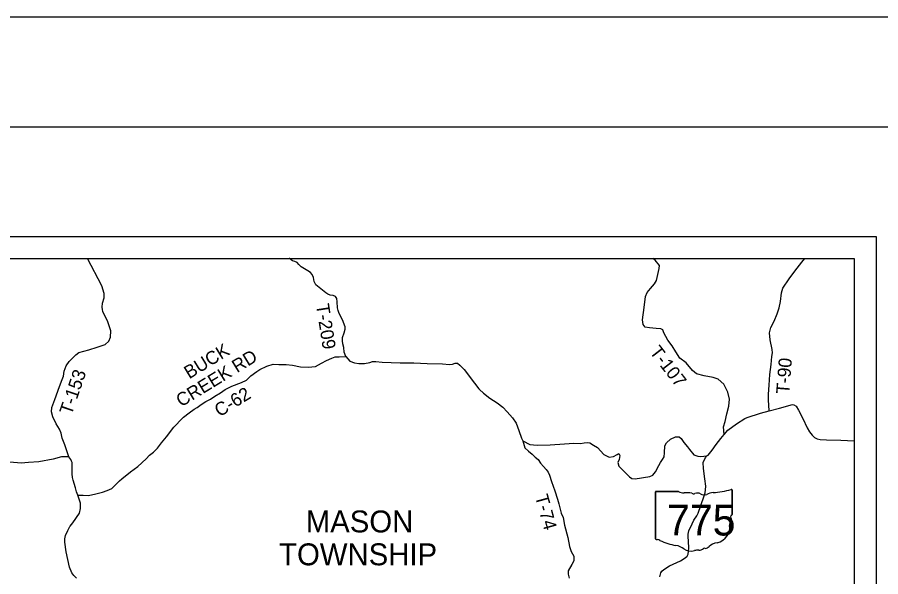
# Model space of a CAD drawing. Extents: x -6.4 to 34, y -1.2 to 22.
# Drawn here: x 5.084 to 9.021, y 19.448 to 22 of the extents above; entities that cross this region are included whole.
import ezdxf

# ---------------------------------------------------------------- set-up
doc = ezdxf.new("R2010")
doc.units = 0
for name, color, linetype in [('GM_X_County', 7, 'Continuous'), ('GM_X_County_ROW', 7, 'Continuous'), ('GM_X_Minor_Lake', 7, 'Continuous'), ('GM_X_Minor_River', 7, 'Continuous'), ('GM_X_Minor_River_Text', 7, 'Continuous'), ('GM_X_Section', 7, 'Continuous'), ('GM_X_Township', 7, 'Continuous'), ('GM_X_Township_Road', 7, 'Continuous'), ('GM_X_Township_Subdivision', 7, 'Continuous'), ('GM_X_Township_Subdivision_Text', 7, 'Continuous'), ('GM_X_Township_Text', 7, 'Continuous')]:
    doc.layers.add(name, color=color, linetype=linetype)

msp = doc.modelspace()

# ---------------------------------------------------------------- linework, layer by layer
at = {"layer": 'GM_X_County'}
msp.add_lwpolyline([(1.5, 21.5), (33.5, 21.5), (33.5, 0.5), (1.5, 0.5)], close=True, dxfattribs=at)
at = {"layer": 'GM_X_County_ROW'}
for p, q in [((7.9936, 19.8336), (7.9936, 19.621)), ((8.0996, 19.8372), (7.9971, 19.8372)), ((8.3437, 19.7313), (8.3437, 19.8425)), ((8.3437, 19.7313), (8.3437, 19.7313))]:
    msp.add_line(p, q, dxfattribs=at)
for centre, major_axis, start_param, end_param in [((8.219, 20.1271), (0.3713, 0), 4.814394, 5.042369), ((8.3398, 19.843), (0.0039, 0), 6.141152, 7.989035), ((7.9976, 19.834), (0.00406, 0), 1.712693, 3.28349), ((8.124, 19.8619), (0.0393, 0), 4.042523, 4.731795), ((8.1371, 19.7179), (0.1412, 0), 1.404758, 1.657858), ((8.1691, 19.8351), (0.0113, 0), 3.836095, 5.185415), ((8.1858, 19.8106), (0.0236, 0), 0.950623, 2.079405), ((8.2162, 19.8443), (0.0284, 0), 4.081561, 5.145723), ((8.2664, 19.7723), (0.0747, 0), 1.699011, 2.107814), ((8.3396, 19.7309), (0.00417, 0), 5.05454, 6.418171), ((8.3577, 19.6848), (0.0263, 0), 2.387724, 3.262537), ((8.3428, 19.7232), (0.00603, 0), 1.883978, 3.671073), ((8.3045, 19.7091), (0.0362, 0), 5.934695, 6.695948), ((8.2398, 19.6706), (0.0929, 0), 5.101752, 6.440018), ((7.9977, 19.6206), (0.00409, 0), 3.00124, 4.508301), ((7.9983, 19.6423), (0.0312, 0), 4.665946, 4.897461), ((8.0047, 19.6088), (0.0113, 0), 0.519207, 1.627899), ((8.1468, 19.7997), (0.2681, 0), 4.195997, 4.488961), ((8.0669, 19.5255), (0.0839, 0), 0.823519, 1.323587), ((8.1576, 19.6077), (0.0532, 0), 4.026481, 4.996735), ((8.1923, 19.5918), (0.0284, 0), 4.691044, 5.507374), ((8.2179, 19.5712), (0.00798, 0), 1.147584, 2.315152), ((8.2145, 19.6004), (0.03, 0), 4.937069, 5.64225), ((8.279, 19.5613), (0.0509, 0), 1.647645, 2.488434), ((8.1884, 19.5342), (0.0437, 0), 1.495662, 1.94098)]:
    msp.add_ellipse(centre, major_axis=major_axis, ratio=0.8, start_param=start_param, end_param=end_param, dxfattribs=at)
at = {"layer": 'GM_X_Minor_Lake'}
for points in [[(8.014, 19.4471), (8.0188, 19.4653), (8.0231, 19.4728), (8.0331, 19.481), (8.0579, 19.4977), (8.1083, 19.5209), (8.1301, 19.5342), (8.139, 19.5417), (8.1433, 19.5515), (8.1459, 19.5777), (8.1445, 19.6107), (8.1433, 19.6293), (8.1434, 19.6415), (8.1471, 19.6566), (8.1616, 19.6891), (8.169, 19.706), (8.1822, 19.7252), (8.1892, 19.738), (8.2146, 19.8124), (8.2205, 19.8309), (8.2226, 19.8438), (8.2232, 19.8609), (8.2199, 19.8947), (8.213, 19.9423), (8.2115, 19.9696), (8.2229, 19.9915), (8.2291, 19.9998), (8.234, 20.0031), (8.2529, 20.0259), (8.2703, 20.0504), (8.2927, 20.0785), (8.307, 20.097), (8.3236, 20.1168), (8.3638, 20.1447), (8.4025, 20.1703), (8.4124, 20.1747), (8.4737, 20.1943), (8.5133, 20.2051), (8.5594, 20.2169), (8.5974, 20.2278), (8.6127, 20.2317), (8.6195, 20.2328), (8.6259, 20.2319), (8.6353, 20.2253), (8.6468, 20.2073), (8.6663, 20.1694), (8.6866, 20.127), (8.6962, 20.1086), (8.7085, 20.0929), (8.7201, 20.0832), (8.7313, 20.077), (8.7449, 20.0737), (8.7737, 20.0725), (8.8401, 20.0712), (8.9, 20.067)], [(5.3515, 19.8467), (5.3499, 19.8532), (5.3386, 19.8876), (5.3354, 19.9002), (5.3341, 19.9165), (5.3336, 19.9605), (5.3334, 19.9685), (5.3316, 19.9746), (5.3283, 19.9823), (5.3193, 19.9942), (5.3148, 19.9946), (5.2985, 19.9952), (5.2852, 19.9947), (5.2468, 19.9842), (5.1822, 19.9715), (5.1351, 19.9688), (5.101, 19.9666), (5.0495, 19.9712)], [(5.3241, 19.6767), (5.325, 19.6782), (5.3377, 19.6932), (5.3672, 19.7372), (5.372, 19.7591), (5.3724, 19.7827), (5.3598, 19.8192), (5.3545, 19.8346), (5.3515, 19.8467)], [(5.3537, 19.4409), (5.3414, 19.4536), (5.3329, 19.4663), (5.3223, 19.4922), (5.3066, 19.5608), (5.3008, 19.6057), (5.301, 19.6201), (5.3039, 19.6356), (5.3145, 19.659), (5.3195, 19.6682), (5.3241, 19.6767)]]:
    msp.add_lwpolyline(points, dxfattribs=at)
at = {"layer": 'GM_X_Minor_River'}
for points in [[(6.176, 20.3834), (6.1761, 20.3834), (6.1906, 20.3938), (6.2224, 20.4087), (6.2511, 20.4172), (6.2769, 20.4166), (6.3102, 20.4164), (6.3383, 20.4123), (6.3747, 20.406), (6.4107, 20.4039), (6.4433, 20.4075), (6.4716, 20.4217), (6.4943, 20.434), (6.5181, 20.4451), (6.5329, 20.4509), (6.5522, 20.4506), (6.5825, 20.4519), (6.6008, 20.4311), (6.6213, 20.4232), (6.6418, 20.4203), (6.6672, 20.4208), (6.6914, 20.4258), (6.7035, 20.4297), (6.7191, 20.4298), (6.7471, 20.4269), (6.8298, 20.4238), (6.8916, 20.423), (6.9526, 20.421), (7.0231, 20.4187), (7.0553, 20.4166), (7.0689, 20.4182), (7.0814, 20.4216), (7.092, 20.4217), (7.1023, 20.4134), (7.1214, 20.3934), (7.1694, 20.3302)], [(5.3598, 19.8192), (5.3836, 19.8194), (5.4083, 19.8191), (5.442, 19.8257), (5.4726, 19.8339), (5.4931, 19.8408), (5.5154, 19.8504), (5.5342, 19.8699), (5.5504, 19.8851), (5.5613, 19.8943), (5.6006, 19.9264), (5.6338, 19.9512), (5.6722, 19.9864), (5.6873, 20.002), (5.7047, 20.0161), (5.7231, 20.0341), (5.7415, 20.0592), (5.7641, 20.0859), (5.7984, 20.1298), (5.8108, 20.1435), (5.8236, 20.1569), (5.8417, 20.1759), (5.8673, 20.1962), (5.89, 20.2123), (5.9047, 20.2196), (5.9228, 20.2329), (5.944, 20.2471), (5.9651, 20.2574), (5.9848, 20.2708), (6.0108, 20.2869), (6.0323, 20.3022), (6.0622, 20.3172), (6.1064, 20.3333), (6.1295, 20.3445), (6.1487, 20.3639), (6.176, 20.3834)], [(7.1694, 20.3302), (7.1695, 20.3301), (7.189, 20.3044), (7.192, 20.3015), (7.2096, 20.2848), (7.2381, 20.2629), (7.2716, 20.2418), (7.2986, 20.221), (7.3184, 20.1995), (7.3417, 20.1726), (7.3593, 20.1488), (7.3716, 20.115), (7.3835, 20.0798), (7.3897, 20.0676)], [(7.3897, 20.0676), (7.4216, 20.0507), (7.4554, 20.0482), (7.5133, 20.0489), (7.58, 20.0537), (7.6224, 20.0566), (7.652, 20.0552), (7.6687, 20.058), (7.6846, 20.0607), (7.6948, 20.0589), (7.7119, 20.0483), (7.7306, 20.0366), (7.7592, 20.0049), (7.7831, 19.994), (7.8032, 19.9967), (7.8202, 20.0059), (7.8274, 20.0094), (7.8323, 20.0003), (7.8283, 19.9832), (7.8231, 19.9683), (7.8269, 19.9528), (7.8753, 19.9036), (7.886, 19.8965), (7.9023, 19.8939), (7.9686, 19.9045), (7.9826, 19.9106), (7.9946, 19.9266), (8.0088, 19.9548), (8.0175, 19.9689), (8.0257, 19.9822), (8.0336, 19.9952), (8.035, 20.0134), (8.0375, 20.0449), (8.0446, 20.0586), (8.0631, 20.0754), (8.0858, 20.0858), (8.1021, 20.0859), (8.1116, 20.0783), (8.1242, 20.0609), (8.1402, 20.0405), (8.1494, 20.0276), (8.1696, 20.0045), (8.1867, 19.9978), (8.2015, 19.9956), (8.2291, 19.9998)]]:
    msp.add_lwpolyline(points, dxfattribs=at)
at = {"layer": 'GM_X_Minor_River_Text'}
for points in [[(5.4706, 20.6759), (5.4706, 20.6761), (5.4702, 20.6781), (5.4729, 20.6963), (5.4794, 20.7195), (5.4798, 20.74), (5.4692, 20.7746), (5.4034, 20.9)], [(6.5825, 20.4519), (6.5748, 20.4725), (6.5726, 20.493), (6.5688, 20.5105), (6.5662, 20.5238), (6.567, 20.5394), (6.5746, 20.5603), (6.5792, 20.5766), (6.5789, 20.5884), (6.5664, 20.62), (6.5521, 20.6485), (6.5472, 20.6626), (6.5442, 20.674), (6.5431, 20.7025), (6.5405, 20.7166), (6.5352, 20.7261), (6.5245, 20.731), (6.5101, 20.733), (6.5007, 20.7372), (6.4908, 20.7425), (6.4461, 20.7799), (6.4382, 20.7947), (6.4344, 20.8122), (6.4284, 20.8263), (6.4208, 20.8362), (6.4091, 20.8434), (6.3784, 20.8614), (6.3674, 20.872), (6.3598, 20.8812), (6.3492, 20.8854), (6.3393, 20.8892), (6.3249, 20.8991), (6.3242, 20.9)], [(8.307, 20.097), (8.3049, 20.132), (8.3116, 20.1556), (8.3194, 20.1906), (8.329, 20.226), (8.3311, 20.2575), (8.3245, 20.2894), (8.3065, 20.3269), (8.2806, 20.3488), (8.2578, 20.3563), (8.2161, 20.3641), (8.1815, 20.3738), (8.1629, 20.3889), (8.1335, 20.4233), (8.1057, 20.4456), (8.087, 20.4736), (8.0705, 20.5016), (8.0506, 20.5277), (8.033, 20.5611), (8.0273, 20.5736), (8.0189, 20.5781), (7.9969, 20.5807), (7.9666, 20.5828), (7.9476, 20.5869), (7.9384, 20.5982), (7.9357, 20.6202), (7.9423, 20.6765), (7.9483, 20.7267), (7.9558, 20.7442), (7.9716, 20.7632), (7.9904, 20.7835), (7.9987, 20.7995), (8.0116, 20.8534), (8.0119, 20.8675), (7.9928, 20.8913), (7.9823, 20.9)], [(8.5133, 20.2051), (8.5105, 20.2307), (8.5094, 20.2535), (8.5099, 20.2809), (8.5122, 20.3223), (8.5158, 20.3709), (8.5216, 20.4157), (8.5255, 20.4518), (8.5285, 20.4693), (8.5271, 20.4849), (8.5169, 20.5286), (8.5136, 20.5598), (8.5205, 20.5845), (8.5357, 20.6137), (8.5491, 20.6471), (8.5579, 20.6748), (8.5644, 20.7037), (8.569, 20.7428), (8.5751, 20.7649), (8.6037, 20.8066), (8.6303, 20.8411), (8.6616, 20.8824), (8.6757, 20.9)], [(5.3193, 19.9942), (5.3126, 20.0123), (5.3002, 20.0499), (5.2892, 20.08), (5.2836, 20.102), (5.2761, 20.1207), (5.2606, 20.1458), (5.2458, 20.1777), (5.2394, 20.2006), (5.241, 20.2196), (5.2547, 20.2564), (5.2761, 20.3149), (5.2884, 20.3471), (5.2941, 20.3631), (5.2972, 20.3851), (5.3063, 20.4094), (5.3208, 20.4291), (5.3345, 20.4428), (5.3512, 20.4598), (5.3649, 20.4701), (5.4094, 20.4829), (5.4481, 20.4946), (5.4853, 20.5074), (5.5009, 20.5218), (5.5085, 20.54), (5.5101, 20.5689), (5.4947, 20.6153), (5.4747, 20.656), (5.472, 20.669), (5.4706, 20.6759)], [(7.3897, 20.0676), (7.399, 20.0358), (7.4146, 20.021), (7.4325, 20.0075), (7.4462, 19.9935), (7.4595, 19.9825), (7.4699, 19.9662), (7.484, 19.95), (7.4962, 19.9375), (7.5046, 19.925), (7.5115, 19.9114), (7.5207, 19.8818), (7.5358, 19.8397), (7.5481, 19.8014), (7.5535, 19.7809), (7.559, 19.7555), (7.5636, 19.7373), (7.5728, 19.7187), (7.5799, 19.6823), (7.5938, 19.6262), (7.602, 19.5856), (7.6097, 19.5632), (7.6212, 19.5412), (7.6225, 19.5211), (7.6124, 19.5032), (7.5962, 19.475), (7.5956, 19.4591), (7.6013, 19.4416)]]:
    msp.add_lwpolyline(points, dxfattribs=at)
at = {"layer": 'GM_X_Section'}
msp.add_lwpolyline([(0, 0), (34, 0), (34, 22), (0, 22)], close=True, dxfattribs=at)
at = {"layer": 'GM_X_Township'}
for p, q in [((2, 21), (9, 21)), ((9, 21), (9, 14)), ((2.1, 20.9), (8.9, 20.9)), ((8.9, 20.9), (8.9, 14.1))]:
    msp.add_line(p, q, dxfattribs=at)
at = {"layer": 'GM_X_Township_Road'}
for p, q in [((7.9936, 19.621), (7.9936, 19.8336)), ((7.9971, 19.8373), (8.0996, 19.8373)), ((8.3437, 19.8425), (8.3437, 19.7313)), ((8.341, 19.7277), (8.341, 19.7277))]:
    msp.add_line(p, q, dxfattribs=at)
for centre, major_axis, start_param, end_param in [((8.219, 20.1271), (0.3713, 0), 4.814394, 5.042369), ((8.3398, 19.843), (0.0039, 0), 6.141152, 7.989035), ((7.9976, 19.834), (0.00406, 0), 1.712693, 3.28349), ((8.124, 19.8619), (0.0393, 0), 4.042523, 4.731795), ((8.1371, 19.7179), (0.1412, 0), 1.404758, 1.657858), ((8.1691, 19.8351), (0.0113, 0), 3.836095, 5.185415), ((8.1858, 19.8106), (0.0236, 0), 0.950623, 2.079405), ((8.2162, 19.8443), (0.0284, 0), 4.081561, 5.145723), ((8.2664, 19.7723), (0.0747, 0), 1.699011, 2.107814), ((8.3396, 19.7309), (0.00417, 0), 5.05454, 6.418171), ((8.3577, 19.6848), (0.0263, 0), 2.387724, 3.262537), ((8.3428, 19.7232), (0.00603, 0), 1.883978, 3.671073), ((8.3045, 19.7091), (0.0362, 0), 5.934695, 6.695948), ((8.2398, 19.6706), (0.0929, 0), 5.101752, 6.440018), ((7.9977, 19.6206), (0.00409, 0), 3.00124, 4.508301), ((7.9983, 19.6423), (0.0312, 0), 4.665946, 4.897461), ((8.0047, 19.6088), (0.0113, 0), 0.519207, 1.627899), ((8.1468, 19.7997), (0.2681, 0), 4.195997, 4.488961), ((8.0669, 19.5255), (0.0839, 0), 0.823519, 1.323587), ((8.1576, 19.6077), (0.0532, 0), 4.026481, 4.996735), ((8.1923, 19.5918), (0.0284, 0), 4.691044, 5.507374), ((8.2179, 19.5712), (0.00798, 0), 1.147584, 2.315152), ((8.2145, 19.6004), (0.03, 0), 4.937069, 5.64225), ((8.279, 19.5613), (0.0509, 0), 1.647645, 2.488434), ((8.1884, 19.5342), (0.0437, 0), 1.495662, 1.94098)]:
    msp.add_ellipse(centre, major_axis=major_axis, ratio=0.8, start_param=start_param, end_param=end_param, dxfattribs=at)

# ---------------------------------------------------------------- texts
at = {"layer": 'GM_X_County_ROW'}
msp.add_text('775', height=0.14004, dxfattribs=at).set_placement((8.0467, 19.636))
at = {"layer": 'GM_X_Township_Subdivision'}
for s, rotation, p in [('T-209', 278.9255, (6.4456, 20.6886)), ('T-107', 307.669, (7.9648, 20.4727)), ('T-90', 85.3803, (8.6037, 20.2794)), ('T-153', 71.0094, (5.331, 20.1822)), ('T-74', 285.4163, (7.4442, 19.8145))]:
    msp.add_text(s, height=0.06, rotation=rotation, dxfattribs=at).set_placement(p)
at = {"layer": 'GM_X_Township_Subdivision_Text'}
for s, p in [('MASON', (6.3995, 19.65)), ('TOWNSHIP', (6.2778, 19.5))]:
    msp.add_text(s, height=0.1, dxfattribs=at).set_placement(p)
at = {"layer": 'GM_X_Township_Text'}
for s, p in [('CREEK RD', (5.8312, 20.2202)), ('BUCK', (5.8678, 20.3481)), ('C-62', (6.0063, 20.1749))]:
    msp.add_text(s, height=0.06, rotation=31.4456, dxfattribs=at).set_placement(p)

doc.saveas('drawing.dxf')
